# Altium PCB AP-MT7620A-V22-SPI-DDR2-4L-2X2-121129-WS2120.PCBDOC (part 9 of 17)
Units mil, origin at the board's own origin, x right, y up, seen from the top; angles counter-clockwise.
Board outline 7316 x 4279 mil, 4 copper layers (Top, Inner Layer 2, Inner Layer 3, Bottom), stack 35.4 mil thick; 640 components, 473 nets, 2041 pads, 2358 vias.
Unrouted connection lines stored in the file: 11.
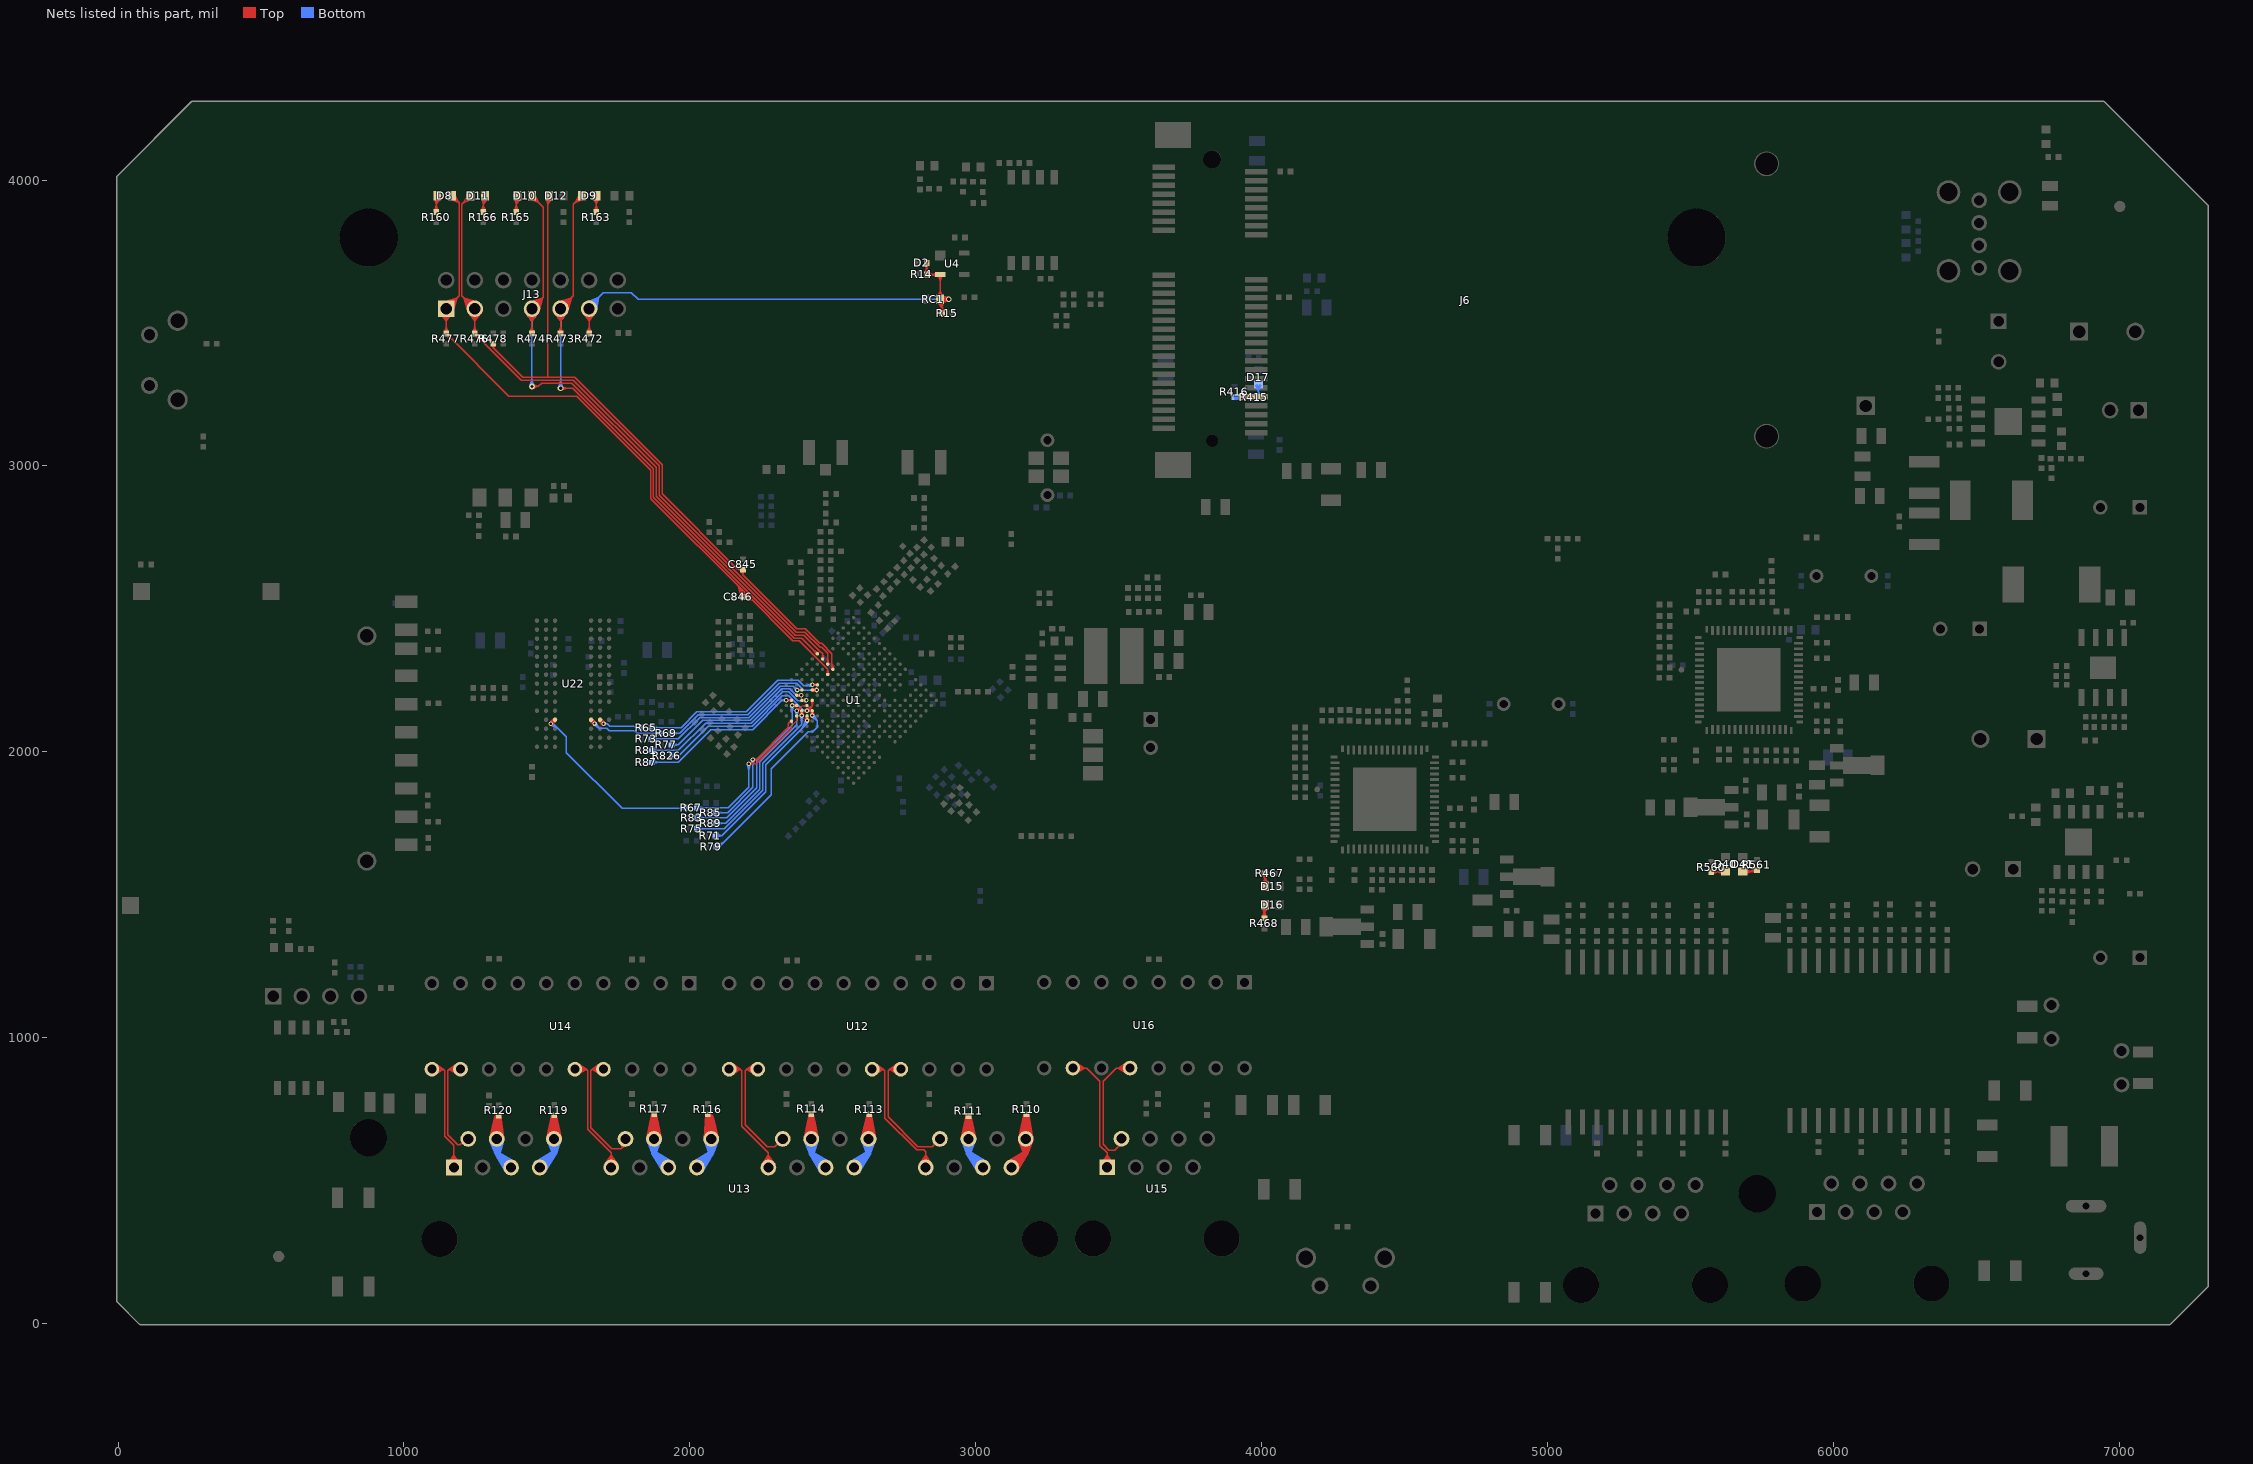
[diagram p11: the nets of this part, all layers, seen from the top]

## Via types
v1: diameter 20, hole 12, Top to Bottom, 2117 vias
v2: diameter 16, hole 8, Top to Bottom, 241 vias

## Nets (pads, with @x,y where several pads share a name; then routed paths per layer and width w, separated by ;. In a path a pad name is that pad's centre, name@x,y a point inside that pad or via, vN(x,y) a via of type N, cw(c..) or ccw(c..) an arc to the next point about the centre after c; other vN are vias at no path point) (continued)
JTAGRST_N: D2.1 J13.11 R14.2 R15.1 R472.2 RC1.1 U4.2 | length 4977.9
  Top w4.5: J13.11@1622.61,3541.58 1648,3507.5 ; J13.11@1626.53,3544.18 1648,3507.5 ; J13.11@1630.64,3546.29 1648,3507.5 ; J13.11@1634.91,3547.93 1648,3507.5 ; J13.11@1639.3,3549.1 1648,3507.5 ; R472.2@1640.36,3464.28 1648,3486.5 ; R472.2@1644.76,3463.22 1648,3486.5 ; R472.2@1648,3463 J13.11@1648,3550 ; R472.2@1651.24,3463.22 1648,3486.5 ; R472.2@1655.64,3464.28 1648,3486.5 ; J13.11@1656.7,3549.1 1648,3507.5 ; J13.11@1661.09,3547.93 1648,3507.5 ; J13.11@1665.36,3546.29 1648,3507.5 ; J13.11@1669.47,3544.18 1648,3507.5 ; J13.11@1673.39,3541.58 1648,3507.5 ; D2.1@2821.36,3708.72 2829,3686.5 ; R14.2@2822.31,3670.95 2829,3693.53 ; D2.1@2825.76,3709.78 2829,3686.5 ; R14.2@2826.75,3670.09 2829,3693.53 ; R14.2@2830.11,3666.75 2853.52,3669.2 ; R14.2@2830.33,3673.23 2853.52,3669.2 ; R14.2@2831.02,3662.32 2853.52,3669.2 ; R14.2@2831.53,3677.6 2853.52,3669.2 ; D2.1@2832.24,3709.78 2829,3686.5 ; R14.2@2833.23,3670.36 2829,3693.53 ; D2.1@2836.64,3708.72 2829,3686.5 ; R14.2@2837.58,3671.6 2829,3693.53 ; RC1.1@2864.11,3587.51 2875.59,3612.5 ; RC1.1@2865.01,3575.88 2883,3552.18 ; U4.2@2865,3662.48 2843.48,3669.2 ; U4.2@2865,3675.93 2843.48,3669.2 ; U4.2@2865.91,3666.9 2843.48,3669.2 ; U4.2@2865.91,3671.51 2843.48,3669.2 ; U4.2@2866.03,3669.2 2843.48,3669.2 ; RC1.1@2868.4,3585.96 2875.59,3612.5 ; RC1.1@2868.84,3578.35 2883,3552.18 ; U4.2@2868.95,3668.2 2875.59,3646.65 ; RC1.1@2872.84,3585.14 2875.59,3612.5 ; RC1.1@2872.96,3580.19 2883,3552.18 ; U4.2@2873.37,3669.1 2875.59,3646.65 ; R15.1@2874.42,3536.6 2883,3558.53 ; RC1.1@2875.59,3581 2883,3552.18 ; RC1.1@2875.59,3585 2875.59,3612.5 ; RC1.1@2875.73,3580.25 v1@2903.09,3583 ; RC1.1@2875.73,3585.75 v1@2903.09,3583 ; RC1.1@2876.55,3575.81 v1@2903.09,3583 ; RC1.1@2876.55,3590.19 v1@2903.09,3583 ; U4.2@2877.98,3669.08 2875.59,3646.65 ; RC1.1@2878.1,3571.52 v1@2903.09,3583 ; RC1.1@2878.1,3594.48 v1@2903.09,3583 ; RC1.1@2878.28,3581.56 2883,3552.18 ; RC1.1@2878.34,3585.14 2875.59,3612.5 ; R15.1@2878.77,3535.36 2883,3558.53 ; U4.2@2882.4,3668.15 2875.59,3646.65 ; RC1.1@2882.78,3581.94 2883,3552.18 ; RC1.1@2882.78,3585.96 2875.59,3612.5 ; R15.1@2885.25,3535.09 2883,3558.53 ; RC1.1@2887.07,3587.51 2875.59,3612.5 ; RC1.1@2887.32,3581.62 2883,3552.18 ; R15.1@2889.69,3535.95 2883,3558.53 ; v1@2902.07,3576.32 RC1.1@2881.42,3592.95 ; v1@2902.07,3589.68 RC1.1@2881.42,3573.05 ; v1@2903.09,3575.82 RC1.1@2880.84,3589.02 ; v1@2903.09,3590.18 RC1.1@2880.84,3576.98 ; v1@2904.15,3575.47 RC1.1@2880.55,3585.26 ; v1@2904.15,3590.53 RC1.1@2880.55,3580.74 ; v1@2904.6,3580.07 RC1.1@2881.42,3592.95 ; v1@2904.6,3585.93 RC1.1@2881.42,3573.05 ; v1@2904.82,3575.34 RC1.1@2880.5,3583 ; v1@2904.82,3590.66 RC1.1@2880.5,3583 ; v1@2905.05,3579.89 RC1.1@2880.84,3589.02 ; v1@2905.05,3586.11 RC1.1@2880.84,3576.98 ; v1@2905.51,3575.27 RC1.1@2880.55,3580.74 ; v1@2905.51,3579.79 RC1.1@2880.55,3585.26 ; v1@2905.51,3586.21 RC1.1@2880.55,3580.74 ; v1@2905.51,3590.73 RC1.1@2880.55,3585.26 ; v1@2905.79,3579.76 RC1.1@2880.5,3583 ; v1@2905.79,3586.24 RC1.1@2880.5,3583 ; v1@2906.08,3579.75 RC1.1@2880.55,3580.74 ; v1@2906.08,3586.25 RC1.1@2880.55,3585.26 ; v1@2906.56,3579.8 RC1.1@2880.84,3576.98 ; v1@2906.56,3586.2 RC1.1@2880.84,3589.02 ; v1@2906.66,3575.28 RC1.1@2880.84,3576.98 ; v1@2906.66,3590.72 RC1.1@2880.84,3589.02 ; v1@2907.03,3579.92 RC1.1@2881.42,3573.05 ; v1@2907.03,3586.08 RC1.1@2881.42,3592.95 ; v1@2907.83,3575.47 RC1.1@2881.42,3573.05 ; v1@2907.83,3590.53 RC1.1@2881.42,3592.95 ; R14.2@2829,3670 R14.2@2830,3670 ; R14.2@2829,3670 2829.8,3669.2 U4.2@2875.68,3669.2 ; R14.2@2829,3670 D2.1@2829,3710 2829,3686.5 ; 2829,3693.53 R14.2@2830,3670 ; R14.2@2830,3670 2853.52,3669.2 ; RC1.1@2875.59,3583 2875.59,3669.12 U4.2@2875.68,3669.2 ; RC1.1@2875.59,3583 v1(2906,3583) ; RC1.1@2875.59,3583 2883,3575.59 2883,3535 R15.1@2882,3535 2883,3558.53 ; 2875.59,3646.65 U4.2@2875.68,3669.2 ; RC1.1@2880.5,3583 v1(2906,3583) ; RC1.1@2880.55,3580.74 v1(2906,3583) ; RC1.1@2880.55,3585.26 v1(2906,3583) ; RC1.1@2880.84,3576.98 v1(2906,3583) ; RC1.1@2880.84,3589.02 v1(2906,3583) ; RC1.1@2881.42,3573.05 v1(2906,3583) ; RC1.1@2881.42,3592.95 v1(2906,3583)
  Bottom w4.5: J13.11@1632.42,3571.75 1681.31,3590.31 ; J13.11@1634.26,3567.5 1681.31,3590.31 ; J13.11@1636.43,3563.47 1681.31,3590.31 ; J13.11@1638.94,3559.67 1681.31,3590.31 ; J13.11@1641.74,3556.12 1681.31,3590.31 ; J13.11@1648,3550 1650,3552 1650,3561 1652,3561 1697,3606 1796,3606 1819,3583 v1(2906,3583) 2880.5,3583 ; J13.11@1655.19,3545.01 1681.31,3590.31 ; J13.11@1659.2,3542.92 1681.31,3590.31 ; J13.11@1663.4,3541.18 1681.31,3590.31 ; J13.11@1667.78,3539.8 1681.31,3590.31 ; J13.11@1672.29,3538.8 1681.31,3590.31 ; v1@2904.82,3575.34 2880.5,3583 ; v1@2904.82,3590.66 2880.5,3583 ; v1@2905.79,3579.76 2880.5,3583 ; v1@2905.79,3586.24 2880.5,3583
LANLED0_IP1001-2_6-LED1: D40.2 R560.1 | length 363.3
  Top w4.5: R560.1@5572.89,1582.25 5596.71,1581.41 ; R560.1@5573.48,1586.74 5596.71,1581.41 ; R560.1@5573.55,1575.8 5596.71,1581.41 ; R560.1@5575.03,1571.52 5596.71,1581.41 ; D40.2@5618.49,1569.93 5593.5,1581.41 ; D40.2@5618.49,1592.89 5593.5,1581.41 ; D40.2@5620.04,1574.22 5593.5,1581.41 ; D40.2@5620.04,1588.6 5593.5,1581.41 ; D40.2@5620.86,1578.66 5593.5,1581.41 ; D40.2@5620.86,1584.16 5593.5,1581.41 ; D40.2@5621,1581.41 5593.5,1581.41 ; D40.2@5623,1581.41 5574.41,1581.41 5573,1580 R560.1@5573,1579 5596.71,1581.41
LANLED0_IP1001_6-LED1: D15.2 R467.1 | length 358.2
  Top w4.5: D15.2@4000.93,1534.51 4012.41,1559.5 ; R467.1@4002.52,1572.97 4012.41,1551.3 ; D15.2@4005.22,1532.96 4012.41,1559.5 ; R467.1@4006.8,1574.45 4012.41,1551.3 ; D15.2@4009.66,1532.14 4012.41,1559.5 ; D15.2@4012.41,1530 4012.41,1573.59 4011,1575 R467.1@4010,1575 4012.41,1551.3 ; D15.2@4012.41,1532 4012.41,1559.5 ; R467.1@4013.25,1575.11 4012.41,1551.3 ; D15.2@4015.16,1532.14 4012.41,1559.5 ; R467.1@4017.74,1574.52 4012.41,1551.3 ; D15.2@4019.6,1532.96 4012.41,1559.5 ; D15.2@4023.89,1534.51 4012.41,1559.5
LANLED1_6-LED1: D11.1 R166.1 | length 354.9
  Top w4.5: R166.1@1270.36,3889.28 1278,3911.5 ; D11.1@1271.84,3942.88 1278,3914.75 ; R166.1@1274.76,3888.22 1278,3911.5 ; D11.1@1276.36,3943.5 1278,3914.75 ; R166.1@1278,3888 1278,3939.41 D11.1@1283.59,3945 ; D11.1@1280.87,3943.4 1278,3914.75 ; R166.1@1281.24,3888.22 1278,3911.5 ; D11.1@1283.59,3943 1278,3914.75 ; R166.1@1285.64,3889.28 1278,3911.5 ; D11.1@1286.26,3942.34 1278,3914.75 ; D11.1@1290.47,3940.71 1278,3914.75 ; D11.1@1294.41,3938.42 1278,3914.75
LANLED2_6-LED1: D10.1 R165.1 | length 350.7
  Top w4.5: R165.1@1385.36,3889.28 1393,3911.5 ; D10.1@1385.68,3942.38 1393,3915.07 ; R165.1@1389.76,3888.22 1393,3911.5 ; D10.1@1390.16,3943.2 1393,3915.07 ; R165.1@1393,3888 1393,3940.59 D10.1@1397.41,3945 ; D10.1@1394.67,3943.3 1393,3915.07 ; R165.1@1396.24,3888.22 1393,3911.5 ; D10.1@1397.41,3943 1393,3915.07 ; D10.1@1400.1,3942.44 1393,3915.07 ; R165.1@1400.64,3889.28 1393,3911.5 ; D10.1@1404.37,3940.96 1393,3915.07 ; D10.1@1408.38,3938.8 1393,3915.07
LANLED2_IP1001-2_6-LED1: D41.2 R561.1 | length 382
  Top w4.5: D41.2@5683,1581.41 5683,1580 5733,1580 R561.1@5733,1587 ; D41.2@5685,1578.66 5712.53,1580 ; D41.2@5685,1581.41 5712.53,1580 ; D41.2@5685.28,1584.15 5712.53,1580 ; D41.2@5685.58,1574.18 5712.53,1580 ; D41.2@5686.32,1588.54 5712.53,1580 ; D41.2@5686.91,1569.82 5712.53,1580 ; D41.2@5688.09,1592.75 5712.53,1580 ; R561.1@5729.82,1594.07 5708.04,1580 ; R561.1@5731.93,1590.07 5708.04,1580 ; R561.1@5733,1588 R561.1@5733,1587 ; R561.1@5733.68,1583.82 5708.04,1580 ; R561.1@5733.95,1579.31 5708.04,1580 ; 5708.04,1580 R561.1@5733,1587
LANLED2_IP1001_6-LED1: D16.2 R468.1 | length 244
  Top w5: D16.2@4000.99,1461.67 4010,1433.91 ; R468.1@4002.58,1419.12 4010,1443 R468.1@4017.42,1419.12 ; D16.2@4005.91,1462.81 4010,1433.91 ; R468.1@4010,1418 4010,1462.59 D16.2@4012.41,1465 ; D16.2@4012.41,1463 4010,1433.91 ; D16.2@4018.79,1461.75 4010,1433.91 ; D16.2@4023.46,1459.81 4010,1433.91
LANLED3_6-LED1: D9.1 R163.1 | length 343.8
  Top w4.5: D9.1@1662.06,3940.74 1673,3915.49 ; R163.1@1665.36,3889.28 1673,3911.5 ; D9.1@1666.38,3942.2 1673,3915.49 ; R163.1@1669.76,3888.22 1673,3911.5 ; D9.1@1670.84,3942.92 1673,3915.49 ; R163.1@1673,3888 1673,3944.41 D9.1@1673.59,3945 ; D9.1@1673.59,3943 1673,3915.49 ; R163.1@1676.24,3888.22 1673,3911.5 ; D9.1@1676.33,3942.8 1673,3915.49 ; R163.1@1680.64,3889.28 1673,3911.5 ; D9.1@1680.76,3941.89 1673,3915.49 ; D9.1@1685.01,3940.25 1673,3915.49
LANLED4_6-LED1: D8.1 R160.1 | length 352.5
  Top w4.5: R160.1@1105.36,3889.28 1113,3911.5 ; D8.1@1105.68,3942.38 1113,3915.19 ; R160.1@1109.76,3888.22 1113,3911.5 ; D8.1@1110.16,3943.2 1113,3915.19 ; R160.1@1113,3888 1113,3945 D8.1@1117.41,3945 ; D8.1@1114.67,3943.3 1113,3915.19 ; R160.1@1116.24,3888.22 1113,3911.5 ; D8.1@1117.41,3943 1113,3915.19 ; D8.1@1120.1,3942.44 1113,3915.19 ; R160.1@1120.64,3889.28 1113,3911.5 ; D8.1@1124.36,3940.95 1113,3915.19 ; D8.1@1128.38,3938.78 1113,3915.19
LANP0_C1_4-ETHERNET: R120.1 U13.4 U13.5 | length 1035.3
  Top w20: U13.4@1307.56,648.06 R120.1@1325,721 ; U13.4@1307.76,649.35 R120.1@1332,728 ; U13.4@1325,654.16 R120.1@1332,728 ; U13.4@1342.44,648.06 R120.1@1325,721 ; U13.4@1342.55,646.38 R120.1@1332,728 ; R120.1@1325,721 U13.4@1325,646 R120.1@1332,728 ; R120.1@1325,721 R120.1@1332,728
  Bottom w20: U13.4@1307.87,642.12 1328,593 ; U13.4@1342.45,644.08 1328,593 ; U13.5@1361.05,535.33 1328,593 ; U13.5@1385.67,559.95 1328,593 ; 1328,593 U13.5@1375,546 1328,593 ; 1328,593 1328,643 U13.4@1325,646 1328,593
LANP0_C2_4-ETHERNET: R119.1 U13.7 U13.8 | length 980.1
  Top w20: U13.8@1507.54,647.88 R119.1@1525,728 ; U13.8@1507.56,648.07 R119.1@1526,729 ; U13.8@1525,658.96 R119.1@1526,729 ; U13.8@1542.46,647.88 R119.1@1525,728 ; U13.8@1542.48,647.65 R119.1@1526,729 ; R119.1@1525,728 U13.8@1525,646 R119.1@1526,729 ; R119.1@1525,728 R119.1@1526,729
  Bottom w20: U13.7@1464.16,559.81 1527,598 ; U13.7@1475,546 1527,598 ; U13.7@1488.81,535.16 1527,598 ; U13.8@1507.89,642.08 1527,598 ; U13.8@1542.38,643.51 1527,598 ; 1527,598 1527,644 U13.8@1525,646 1527,598
LANP1_C1_4-ETHERNET: R117.1 U13.12 U13.13 | length 1073.3
  Top w20: U13.12@1857.53,647.79 R117.1@1875,732 ; U13.12@1857.55,647.97 R117.1@1876,733 ; U13.12@1875,662.96 R117.1@1876,733 ; U13.12@1892.47,647.79 R117.1@1875,732 ; U13.12@1892.49,647.57 R117.1@1876,733 ; R117.1@1875,732 U13.12@1875,646 R117.1@1876,733 ; R117.1@1875,732 R117.1@1876,733
  Bottom w20: U13.12@1857.71,642.92 1875,596 ; U13.12@1892.29,642.92 1875,596 ; U13.13@1911.14,535.22 1875,596 ; U13.13@1935.78,559.86 1875,596 ; 1875,596 U13.13@1925,546 1875,596 ; 1875,596 U13.12@1875,646 1875,596
LANP1_C2_4-ETHERNET: R116.1 U13.15 U13.16 | length 1022.3
  Top w20: U13.16@2057.45,645.34 R116.1@2063,732 ; U13.16@2057.56,648.06 2075,721 ; U13.16@2075,657.42 R116.1@2063,732 ; U13.16@2092.06,650.17 R116.1@2063,732 ; U13.16@2092.44,648.06 2075,721 ; R116.1@2063,732 2064,732 2075,721 ; R116.1@2063,732 2075,721 ; R116.1@2063,732 2075,721 ; R116.1@2063,732 U13.16@2075,646 2075,721
  Bottom w20: U13.15@2014.22,559.86 2075,596 ; U13.15@2025,546 2075,596 ; U13.15@2038.86,535.22 2075,596 ; U13.16@2057.71,642.92 2075,596 ; U13.16@2092.29,642.92 2075,596 ; 2075,596 U13.16@2075,646 2075,596
LANP2_C1_4-ETHERNET: R114.1 U13.20 U13.21 | length 1073.6
  Top w20: U13.20@2425,663 R114.1@2425,733 ; R114.1@2425,733 U13.20@2425,646 R114.1@2425,733 ; R114.1@2425,733 2407.53,647.77 R114.1@2425,733 ; R114.1@2425,733 2442.47,647.77 R114.1@2425,733
  Bottom w20: U13.20@2407.77,642.64 2426,595 ; U13.20@2442.35,643.32 2426,595 ; U13.21@2461.11,535.26 2426,595 ; U13.21@2485.74,559.89 2426,595 ; 2426,595 U13.21@2475,546 2426,595 ; 2426,595 2426,645 U13.20@2425,646 2426,595
LANP2_C2_4-ETHERNET: R113.1 U13.23 U13.24 | length 1091.7
  Top w20: U13.24@2628,662 R113.1@2628,732 ; U13.24@2625,646 2628,643 R113.1@2628,732 ; U13.24@2625,646 R113.1@2628,732 ; U13.24@2625,646 R113.1@2628,732 ; R113.1@2628,732 2607.61,648.4 R113.1@2628,732 ; R113.1@2628,732 2642.52,647.18 R113.1@2628,732
  Bottom w20: U13.23@2564.22,559.86 2625,596 ; U13.23@2575,546 2625,596 ; U13.23@2588.86,535.22 2625,596 ; U13.24@2607.71,642.92 2625,596 ; U13.24@2642.29,642.92 2625,596 ; 2625,596 U13.24@2625,646 2625,596
LANP3_C1_4-ETHERNET: R111.1 U13.28 U13.29 | length 1032.8
  Top w20: U13.28@2975,656 R111.1@2975,726 ; R111.1@2975,726 U13.28@2975,646 R111.1@2975,726 ; R111.1@2975,726 2957.55,647.93 R111.1@2975,726 ; R111.1@2975,726 2992.45,647.93 R111.1@2975,726
  Bottom w20: U13.28@2957.71,642.92 2975,596 ; U13.28@2992.29,642.92 2975,596 ; U13.29@3011.14,535.22 2975,596 ; U13.29@3035.78,559.86 2975,596 ; 2975,596 U13.29@3025,546 2975,596 ; 2975,596 U13.28@2975,646 2975,596
LANP3_C2_4-ETHERNET: R110.1 U13.31 U13.32 | length 994.1
  Top w20: U13.31@3114.22,559.86 3175,596 ; U13.31@3125,546 3175,596 ; U13.31@3138.86,535.22 3175,596 ; U13.32@3157.54,647.86 R110.1@3175,729 ; U13.32@3157.61,648.4 R110.1@3178,732 ; U13.32@3157.71,642.92 3175,596 ; U13.32@3175,661.51 R110.1@3178,732 ; U13.32@3192.29,642.92 3175,596 ; U13.32@3192.46,647.86 R110.1@3175,729 ; U13.32@3192.52,647.18 R110.1@3178,732 ; 3175,596 U13.32@3175,646 ; 3175,596 U13.32@3175,646 ; U13.32@3175,646 R110.1@3175,729 ; U13.32@3175,646 R110.1@3178,732 ; R110.1@3175,729 R110.1@3178,732
LED_5592_5G: D17.2 R415.1 | length 342.6
  Bottom w4: D17.2@3977.32,3281.64 3989,3258.41 ; D17.2@3981.1,3283.18 3989,3258.41 ; R415.1@3983.03,3240.73 3989,3262.11 ; D17.2@3985.01,3284.1 3989,3258.41 ; R415.1@3987,3240 3989,3262.11 ; R415.1@3988,3238 3989,3239 D17.2@3989,3284.41 3989,3258.41 ; R415.1@3991,3240 3989,3262.11 ; D17.2@3992.99,3284.1 3989,3258.41 ; R415.1@3994.94,3240.72 3989,3262.11 ; D17.2@3996.9,3283.18 3989,3258.41 ; R415.1@3998.71,3242.14 3989,3262.11 ; D17.2@4000.68,3281.64 3989,3258.41
  Bottom w4.5: R415.1@3988,3238 R415.1@3990,3240
LED_LKACT#_A_3-WLAN: J6.44 R415.2 R416.2 | length 2386.9
  Top w4: v1@3926.99,3247.74 J6.44@3949.8,3249.55 ; v1@3927.66,3243.77 J6.44@3949.8,3249.55 ; v1@3928.3,3232.03 J6.44@3949.8,3234.15 ; v1@3928.28,3236.07 J6.44@3949.8,3234.15 ; v1@3928.34,3243.95 J6.44@3950.95,3245.68 ; v1@3928.39,3247.98 J6.44@3950.95,3245.68 ; v1@3929,3236 J6.44@3950.95,3238.02 ; v1@3929.02,3244 J6.44@3953.07,3241.85 ; v1@3929.03,3244 J6.44@3951.31,3241.85 ; v1@3929.64,3236.05 J6.44@3953.07,3241.85 ; v1@3929.69,3236.06 J6.44@3951.31,3241.85 ; v1@3929.72,3243.93 J6.44@3950.95,3238.02 ; v1@3929.72,3247.97 J6.44@3953.07,3241.85 ; v1@3929.74,3232.03 J6.44@3950.95,3238.02 ; v1@3929.77,3247.96 J6.44@3951.31,3241.85 ; v1@3930.34,3236.23 J6.44@3950.95,3245.68 ; v1@3930.43,3243.73 J6.44@3949.8,3234.15 ; v1@3930.93,3232.24 J6.44@3953.07,3241.85 ; v1@3930.98,3236.52 J6.44@3949.8,3249.55 ; v1@3931.08,3232.27 J6.44@3951.31,3241.85 ; v1@3931.15,3247.71 J6.44@3950.95,3238.02 ; v1@3932.34,3232.73 J6.44@3950.95,3245.68 ; v1@3932.55,3247.17 J6.44@3949.8,3234.15 ; v1@3933.56,3233.42 J6.44@3949.8,3249.55 ; J6.44@3962,3241.85 v1@3930.85,3241.85 ; v1(3929,3240) v1@3930.85,3241.85 ; v1(3929,3240) J6.44@3953.07,3241.85 ; v1(3929,3240) J6.44@3949.8,3234.15 ; v1(3929,3240) J6.44@3949.8,3249.55 ; v1(3929,3240) J6.44@3950.95,3238.02 ; v1(3929,3240) J6.44@3950.95,3245.68 ; v1(3929,3240) J6.44@3951.31,3241.85 ; v1@3930.85,3241.85 J6.44@3949.8,3234.15 ; v1@3930.85,3241.85 J6.44@3949.8,3249.55 ; v1@3930.85,3241.85 J6.44@3950.95,3238.02 ; v1@3930.85,3241.85 J6.44@3950.95,3245.68 ; v1@3930.85,3241.85 J6.44@3951.31,3241.85
  Top w4.5: J6.44@3962,3241.85 J6.44@3980.83,3241.85
  Bottom w4: v1@3924.92,3233.12 R416.2@3906.09,3248.92 ; v1@3925.38,3247.13 R416.2@3906.81,3233.21 ; v1@3926.09,3232.55 R416.2@3905.19,3244.99 ; v1@3926.67,3247.65 R416.2@3905.54,3237.04 ; v1@3927.02,3232.25 R416.2@3905,3242 ; v1@3927.25,3236.4 R416.2@3906.09,3248.92 ; v1@3927.34,3232.17 R416.2@3905,3241 ; v1@3927.5,3243.71 R416.2@3906.81,3233.21 ; v1@3927.85,3232.08 R415.2@3952.5,3232.54 ; v1@3927.86,3236.17 R416.2@3905.19,3244.99 ; v1@3927.85,3247.92 R415.2@3952.5,3247.46 ; v1@3928,3247.94 R416.2@3905,3241 ; v1@3928.1,3236.1 R415.2@3952.5,3232.54 ; v1@3928.1,3243.9 R415.2@3952.5,3247.46 ; v1@3928.16,3243.91 R416.2@3905.54,3237.04 ; v1@3928.34,3236.06 R416.2@3905,3242 ; v1@3928.33,3247.97 R416.2@3905,3242 ; v1@3928.5,3236.03 R416.2@3905,3241 ; v1@3928.65,3232.01 R416.2@3905.54,3237.04 ; v1@3928.72,3236.01 R415.2@3952.88,3236.34 ; v1@3928.72,3243.99 R415.2@3952.88,3243.66 ; v1@3928.83,3244 R416.2@3905,3241 ; v1@3929,3244 R416.2@3905,3242 ; v1@3929.11,3232 R415.2@3952.88,3236.34 ; v1@3929.11,3248 R415.2@3952.88,3243.66 ; v1@3929.16,3236 R416.2@3905.54,3237.04 ; v1@3929.33,3236.01 R415.2@3953,3240 ; v1@3929.33,3243.99 R415.2@3953,3240 ; v1@3929.33,3247.99 R416.2@3905.19,3244.99 ; v1@3929.5,3243.97 R416.2@3905.19,3244.99 ; v1@3929.84,3236.09 R416.2@3906.81,3233.21 ; v1@3929.93,3236.11 R415.2@3952.88,3243.66 ; v1@3929.93,3243.89 R415.2@3952.88,3236.34 ; v1@3929.99,3232.06 R416.2@3906.81,3233.21 ; v1@3930.14,3243.83 R416.2@3906.09,3248.92 ; v1@3930.33,3232.11 R415.2@3953,3240 ; v1@3930.33,3247.89 R415.2@3953,3240 ; v1@3930.52,3236.3 R415.2@3952.5,3247.46 ; v1@3930.52,3243.7 R415.2@3952.5,3232.54 ; v1@3930.65,3247.83 R416.2@3906.09,3248.92 ; v1@3931.5,3232.4 R415.2@3952.88,3243.66 ; v1@3931.5,3247.6 R415.2@3952.88,3236.34 ; v1@3932.63,3232.87 R415.2@3952.5,3247.46 ; v1@3932.63,3247.13 R415.2@3952.5,3232.54 ; R415.2@3953.55,3232.13 v1@3933,3240 ; R415.2@3953.55,3247.87 v1@3933,3240 ; R415.2@3954.64,3236.02 v1@3933,3240 ; R415.2@3954.64,3243.98 v1@3933,3240 ; R415.2@3955,3240 v1(3929,3240) ; R416.2@3905,3241 R416.2@3905,3242 ; R416.2@3905,3241 v1@3927,3242 ; R416.2@3905,3241 v1(3929,3240) ; R416.2@3905,3242 v1@3927,3242 ; R416.2@3905,3242 v1(3929,3240) ; R416.2@3905.18,3245 v1@3927,3242 ; R416.2@3905.19,3244.99 v1(3929,3240) ; R416.2@3905.54,3237.04 v1@3927,3242 ; R416.2@3905.54,3237.04 v1(3929,3240) ; R416.2@3906.09,3248.92 v1@3927,3242 ; R416.2@3906.09,3248.92 v1(3929,3240) ; R416.2@3906.81,3233.21 v1@3927,3242 ; R416.2@3906.81,3233.21 v1(3929,3240) ; v1@3927,3242 v1(3929,3240) ; v1(3929,3240) R415.2@3952.5,3232.54 ; v1(3929,3240) R415.2@3952.5,3247.46 ; v1(3929,3240) R415.2@3952.88,3236.34 ; v1(3929,3240) R415.2@3952.88,3243.66
LINK0: C845.1 D12.2 R478.2 U1.H4 | length 2845.7
  Top w4.5: R478.2@1305.55,3424.85 1313,3413 ; R478.2@1309.77,3426.62 1313,3413 ; R478.2@1313,3427 1313,3413 ; R478.2@1316.23,3426.62 1313,3413 ; R478.2@1320.45,3424.85 1313,3413 ; D12.2@1495.68,3942.38 1503,3914.93 ; D12.2@1500.16,3943.2 1503,3914.93 ; D12.2@1504.67,3943.29 1503,3914.93 ; D12.2@1507.41,3943 1503,3914.93 ; D12.2@1507.41,3945 1503,3945 1503,3310 ; D12.2@1510.1,3942.44 1503,3914.93 ; D12.2@1514.37,3940.97 1503,3914.93 ; D12.2@1518.39,3938.82 1503,3914.93 ; 2165,2640 1903,2902 1903,3005 1598,3310 1503,3310 ; C845.1@2178.41,2636.42 2186,2619 ; C845.1@2182.76,2637.72 2186,2619 ; C845.1@2186,2638 2186,2619 ; C845.1@2189.24,2637.72 2186,2619 ; C845.1@2193.59,2636.42 2186,2619 ; U1.H4@2496.98,2288.27 2497,2310.49 ; U1.H4@2504.16,2289.46 2497,2310.49 ; 1313,3413 1416,3310 1503,3310 ; 2186,2619 2375,2430 2404.43,2430 2455.43,2379 2461,2379 2497,2343 2497,2288.57 U1.H4@2500.62,2288.57 2497,2310.49
  Top w5: 2165,2640 2167,2638 ; C845.1@2184.52,2630.65 2167,2638 ; C845.1@2184.52,2645.35 2167,2638 ; C845.1@2186,2638 2167,2638
LINK1: D11.2 J13.3 R476.2 U1.H3 | length 3799.1
  Top w4.5: J13.3@1222.61,3541.58 1248,3507.5 ; D11.2@1223.02,3950.06 1208.86,3921.45 ; J13.3@1225.02,3536.3 1209.45,3588.55 ; J13.3@1226.53,3544.18 1248,3507.5 ; D11.2@1226.94,3947.76 1208.86,3921.45 ; J13.3@1229.39,3537.81 1209.45,3588.55 ; D11.2@1230.47,3944.95 1208.86,3921.45 ; J13.3@1230.64,3546.29 1248,3507.5 ; D11.2@1232.41,3943 1208.86,3921.45 ; D11.2@1232.41,3945 1203,3915.59 1203,3595 J13.3@1248,3550 R476.2@1248,3463 ; J13.3@1233.57,3539.66 1209.45,3588.55 ; D11.2@1234.18,3940.89 1208.86,3921.45 ; J13.3@1234.91,3547.93 1248,3507.5 ; D11.2@1236.66,3937.13 1208.86,3921.45 ; J13.3@1237.56,3541.84 1209.45,3588.55 ; D11.2@1238.61,3933.02 1208.86,3921.45 ; J13.3@1239.3,3549.1 1248,3507.5 ; R476.2@1240.36,3464.28 1248,3486.5 ; J13.3@1241.34,3544.33 1209.45,3588.55 ; R476.2@1243.19,3456.92 1266.92,3443.08 ; R476.2@1244.76,3463.22 1248,3486.5 ; R476.2@1245.78,3460.63 1266.92,3443.08 ; R476.2@1250.49,3465.1 1266.92,3443.08 ; R476.2@1251.24,3463.22 1248,3486.5 ; J13.3@1253.67,3556.66 1209.45,3588.55 ; R476.2@1254.32,3467.49 1266.92,3443.08 ; R476.2@1255.64,3464.28 1248,3486.5 ; J13.3@1256.16,3560.44 1209.45,3588.55 ; J13.3@1256.7,3549.1 1248,3507.5 ; J13.3@1258.34,3564.43 1209.45,3588.55 ; J13.3@1260.19,3568.61 1209.45,3588.55 ; J13.3@1261.09,3547.93 1248,3507.5 ; J13.3@1261.7,3572.98 1209.45,3588.55 ; J13.3@1265.36,3546.29 1248,3507.5 ; J13.3@1269.47,3544.18 1248,3507.5 ; J13.3@1273.39,3541.58 1248,3507.5 ; U1.H3@2478.88,2306.97 2482.52,2328.52 ; U1.H3@2486.17,2306.97 2482.52,2328.52 ; R476.2@1248,3463 1248,3462 1284,3426 1284,3425.75 1311.75,3398 1312,3398 1410,3300 1593,3300 1893,3000 1893,2898 2373,2418 2402.82,2418 2455.82,2365 2461.57,2365 2482.52,2344.04 U1.H3@2482.52,2306.67 2482.52,2328.52 ; R476.2@1248,3463 1266.92,3443.08
LINK2: D10.2 J13.7 R474.2 U1.H2 | length 4237.6
  Top w4.5: J13.7@1422.61,3541.58 1448,3507.5 ; J13.7@1426.53,3544.18 1448,3507.5 ; J13.7@1430.64,3546.29 1448,3507.5 ; J13.7@1434.3,3572.98 1486.55,3588.55 ; J13.7@1434.91,3547.93 1448,3507.5 ; J13.7@1435.81,3568.61 1486.55,3588.55 ; J13.7@1437.66,3564.43 1486.55,3588.55 ; J13.7@1439.3,3549.1 1448,3507.5 ; J13.7@1439.84,3560.44 1486.55,3588.55 ; R474.2@1440.36,3464.28 1448,3486.5 ; D10.2@1442.11,3933.2 1471.76,3920.65 ; J13.7@1442.33,3556.66 1486.55,3588.55 ; D10.2@1444.18,3937.25 1471.76,3920.65 ; R474.2@1444.76,3463.22 1448,3486.5 ; D10.2@1446.77,3940.94 1471.76,3920.65 ; v1(1448,3278) 1469.66,3278 ; R474.2@1448,3463 J13.7@1448,3550 1488,3590 1488,3904.41 1448,3944.41 D10.2@1448.59,3945 ; v1@1448.24,3274.76 1469.66,3278 ; v1@1448.24,3281.24 1469.66,3278 ; D10.2@1448.59,3943 1471.76,3920.65 ; v1@1449.39,3270.38 1469.66,3278 ; v1@1449.39,3285.62 1469.66,3278 ; D10.2@1450.58,3944.9 1471.76,3920.65 ; R474.2@1451.24,3463.22 1448,3486.5 ; D10.2@1454.18,3947.62 1471.76,3920.65 ; J13.7@1454.66,3544.33 1486.55,3588.55 ; R474.2@1455.64,3464.28 1448,3486.5 ; J13.7@1456.7,3549.1 1448,3507.5 ; D10.2@1458.15,3949.83 1471.76,3920.65 ; J13.7@1458.44,3541.84 1486.55,3588.55 ; J13.7@1461.09,3547.93 1448,3507.5 ; J13.7@1462.43,3539.66 1486.55,3588.55 ; J13.7@1465.36,3546.29 1448,3507.5 ; J13.7@1466.61,3537.81 1486.55,3588.55 ; J13.7@1469.47,3544.18 1448,3507.5 ; J13.7@1470.98,3536.3 1486.55,3588.55 ; J13.7@1473.39,3541.58 1448,3507.5 ; U1.H2@2460.79,2325.12 2464.43,2343.37 ; U1.H2@2468.07,2325.12 2464.43,2343.37 ; 1469.66,3278 1481.66,3290 1588,3290 1883,2995 1883,2894 2369,2408 2399.2,2408 2451.2,2356 2451.8,2356 2464.43,2343.37 ; 2464.43,2343.37 U1.H2@2464.43,2324.76 2464.43,2343.37
  Bottom w4.5: J13.7@1422.61,3541.58 1448,3507.5 ; J13.7@1426.53,3544.18 1448,3507.5 ; J13.7@1430.64,3546.29 1448,3507.5 ; J13.7@1434.91,3547.93 1448,3507.5 ; J13.7@1439.3,3549.1 1448,3507.5 ; v1@1440.34,3279.18 1448,3303.5 ; v1@1444.76,3278.21 1448,3303.5 ; v1(1448,3278) J13.7@1448,3550 ; v1@1451.24,3278.21 1448,3303.5 ; v1@1455.66,3279.18 1448,3303.5 ; J13.7@1456.7,3549.1 1448,3507.5 ; J13.7@1461.09,3547.93 1448,3507.5 ; J13.7@1465.36,3546.29 1448,3507.5 ; J13.7@1469.47,3544.18 1448,3507.5 ; J13.7@1473.39,3541.58 1448,3507.5
LINK3: D9.2 J13.9 R473.2 U1.H1 | length 4107.3
  Top w4.5: J13.9@1522.61,3541.58 1548,3507.5 ; J13.9@1526.53,3544.18 1548,3507.5 ; J13.9@1530.64,3546.29 1548,3507.5 ; J13.9@1534.3,3572.98 1586.55,3588.55 ; J13.9@1534.91,3547.93 1548,3507.5 ; J13.9@1535.81,3568.61 1586.55,3588.55 ; J13.9@1537.66,3564.43 1586.55,3588.55 ; J13.9@1539.3,3549.1 1548,3507.5 ; J13.9@1539.84,3560.44 1586.55,3588.55 ; R473.2@1540.36,3464.28 1548,3486.5 ; J13.9@1542.33,3556.66 1586.55,3588.55 ; R473.2@1544.76,3463.22 1548,3486.5 ; v1(1548,3272) 1591,3272 1873,2990 1873,2890 2365,2398 2391.19,2398 U1.H1@2446.33,2342.86 2432.61,2356.58 ; R473.2@1548,3463 J13.9@1548,3550 1593,3595 1593,3915.59 D9.2@1622.41,3945 ; v1@1548.21,3268.76 1573.5,3272 ; v1@1548.21,3275.24 1573.5,3272 ; v1@1549.18,3264.34 1573.5,3272 ; v1@1549.18,3279.66 1573.5,3272 ; R473.2@1551.24,3463.22 1548,3486.5 ; J13.9@1554.66,3544.33 1586.55,3588.55 ; R473.2@1555.64,3464.28 1548,3486.5 ; J13.9@1556.7,3549.1 1548,3507.5 ; J13.9@1558.44,3541.84 1586.55,3588.55 ; J13.9@1561.09,3547.93 1548,3507.5 ; J13.9@1562.43,3539.66 1586.55,3588.55 ; J13.9@1565.36,3546.29 1548,3507.5 ; J13.9@1566.61,3537.81 1586.55,3588.55 ; J13.9@1569.47,3544.18 1548,3507.5 ; J13.9@1570.98,3536.3 1586.55,3588.55 ; J13.9@1573.39,3541.58 1548,3507.5 ; D9.2@1613.02,3950.06 1598.86,3921.45 ; D9.2@1616.94,3947.76 1598.86,3921.45 ; D9.2@1620.47,3944.95 1598.86,3921.45 ; D9.2@1622.41,3943 1598.86,3921.45 ; D9.2@1624.18,3940.89 1598.86,3921.45 ; D9.2@1626.66,3937.13 1598.86,3921.45 ; D9.2@1628.61,3933.02 1598.86,3921.45 ; U1.H1@2443.52,2340.53 2432.61,2356.58 ; U1.H1@2448.66,2345.67 2432.61,2356.58
  Bottom w4.5: J13.9@1522.61,3541.58 1548,3507.5 ; J13.9@1526.53,3544.18 1548,3507.5 ; J13.9@1530.64,3546.29 1548,3507.5 ; J13.9@1534.91,3547.93 1548,3507.5 ; J13.9@1539.3,3549.1 1548,3507.5 ; v1@1540.34,3273.18 1548,3297.5 ; v1@1544.76,3272.21 1548,3297.5 ; v1(1548,3272) J13.9@1548,3550 ; v1@1551.24,3272.21 1548,3297.5 ; v1@1555.66,3273.18 1548,3297.5 ; J13.9@1556.7,3549.1 1548,3507.5 ; J13.9@1561.09,3547.93 1548,3507.5 ; J13.9@1565.36,3546.29 1548,3507.5 ; J13.9@1569.47,3544.18 1548,3507.5 ; J13.9@1573.39,3541.58 1548,3507.5
LINK4: C846.1 D8.2 J13.1 R477.2 U1.J4 | length 4467.2
  Top w4.5: J13.1@1122.61,3541.58 1148,3507.5 ; J13.1@1126.53,3544.18 1148,3507.5 ; J13.1@1130.64,3546.29 1148,3507.5 ; J13.1@1134.3,3572.98 1186.55,3588.55 ; J13.1@1134.91,3547.93 1148,3507.5 ; J13.1@1135.81,3568.61 1186.55,3588.55 ; J13.1@1137.66,3564.43 1186.55,3588.55 ; J13.1@1139.3,3549.1 1148,3507.5 ; J13.1@1139.84,3560.44 1186.55,3588.55 ; R477.2@1140.36,3464.28 1148,3486.5 ; J13.1@1142.33,3556.66 1186.55,3588.55 ; R477.2@1143.42,3456.75 1167.79,3443.71 ; R477.2@1144.76,3463.22 1148,3486.5 ; R477.2@1145.87,3460.54 1167.79,3443.71 ; R477.2@1150.4,3465.19 1167.79,3443.71 ; R477.2@1151.24,3463.22 1148,3486.5 ; R477.2@1154.13,3467.74 1167.79,3443.71 ; J13.1@1154.66,3544.33 1186.55,3588.55 ; R477.2@1155.64,3464.28 1148,3486.5 ; J13.1@1156.7,3549.1 1148,3507.5 ; J13.1@1158.44,3541.84 1186.55,3588.55 ; J13.1@1161.09,3547.93 1148,3507.5 ; D8.2@1162.39,3933.02 1192.14,3921.45 ; J13.1@1162.43,3539.66 1186.55,3588.55 ; D8.2@1164.34,3937.13 1192.14,3921.45 ; J13.1@1165.36,3546.29 1148,3507.5 ; J13.1@1166.61,3537.81 1186.55,3588.55 ; D8.2@1166.82,3940.89 1192.14,3921.45 ; D8.2@1168.59,3943 1192.14,3921.45 ; D8.2@1168.59,3945 1193,3920.59 1193,3595 J13.1@1148,3550 R477.2@1148,3463 ; J13.1@1169.47,3544.18 1148,3507.5 ; D8.2@1170.53,3944.95 1192.14,3921.45 ; J13.1@1170.98,3536.3 1186.55,3588.55 ; J13.1@1173.39,3541.58 1148,3507.5 ; D8.2@1174.06,3947.76 1192.14,3921.45 ; D8.2@1177.98,3950.06 1192.14,3921.45 ; C846.1@2180.77,2539.2 2169.23,2579.77 ; C846.1@2185.04,2540.67 2169.23,2579.77 ; C846.1@2186.15,2534.47 2218.5,2530.5 ; C846.1@2187.01,2538.91 2218.5,2530.5 ; C846.1@2189.3,2544.98 2218.5,2530.5 ; C846.1@2190.85,2543.56 2169.23,2579.77 ; C846.1@2191.58,2548.88 2218.5,2530.5 ; C846.1@2194.59,2546.07 2169.23,2579.77 ; U1.J4@2478.89,2270.85 2482.52,2288.48 ; U1.J4@2482.52,2270.48 2482.52,2288.48 ; U1.J4@2486.16,2270.85 2482.52,2288.48 ; R477.2@1148,3463 1148,3462 1149.5,3462 1367.5,3244 1604,3244 1863,2985 1863,2886 2195,2554 ; R477.2@1148,3463 1167.79,3443.71 ; 2169.23,2579.77 C846.1@2188,2542 ; C846.1@2182.66,2547.62 2195,2554 ; C846.1@2182.66,2547.62 2195,2554 ; C846.1@2182.66,2547.62 2195,2554 ; C846.1@2185.4,2543.95 2195,2554 ; C846.1@2185.4,2543.95 2195,2554 ; C846.1@2185.4,2543.95 2195,2554 ; C846.1@2188,2542 2195,2549 2195,2554 ; C846.1@2188,2542 2195,2554 ; C846.1@2188,2542 2218.5,2530.5 ; C846.1@2188,2542 2195,2554 ; C846.1@2188,2542 2195,2554 ; C846.1@2190.98,2540.7 2195,2554 ; C846.1@2190.98,2540.7 2195,2554 ; C846.1@2190.98,2540.7 2195,2554 ; 2195,2554 2361,2388 2383,2388 2482.52,2288.48 ; 2195,2554 C846.1@2195.52,2540.12 ; 2195,2554 C846.1@2195.52,2540.12 ; 2195,2554 C846.1@2195.52,2540.12
MA0+_4-ETHERNET: U13.1 U14.11 | length 1214.3
  Top w5: U14.11@1098,890 1137,890 ; U14.11@1098.12,886.91 1137,890 ; U14.11@1098.12,893.09 1137,890 ; U14.11@1098.84,881.95 1137,890 ; U14.11@1098.84,898.05 1137,890 ; U14.11@1100.2,877.1 1137,890 ; U14.11@1100.2,902.9 1137,890 ; U14.11@1102.2,872.4 1137,890 ; U14.11@1102.2,907.6 1137,890 ; U14.11@1104.84,867.94 1137,890 ; U14.11@1104.84,912.06 1137,890 ; U13.1@1151.05,553.38 1175,588.56 ; U13.1@1155.51,550.73 1175,588.56 ; U13.1@1160.18,548.66 1175,588.56 ; U13.1@1165.01,547.19 1175,588.56 ; U13.1@1169.95,546.3 1175,588.56 ; U13.1@1175,546 1175,623.72 1142.5,656.22 1142.5,884.5 1137,890 ; U13.1@1180.05,546.3 1175,588.56 ; U13.1@1184.99,547.19 1175,588.56 ; U13.1@1189.82,548.66 1175,588.56 ; U13.1@1194.49,550.73 1175,588.56 ; U13.1@1198.95,553.38 1175,588.56
MA0-_4-ETHERNET: U13.2 U14.12 | length 753.1
  Top w5: U14.12@1191.16,867.94 1159,890 ; U14.12@1191.16,912.06 1159,890 ; U14.12@1193.8,872.4 1159,890 ; U14.12@1193.8,907.6 1159,890 ; U14.12@1195.8,877.1 1159,890 ; U14.12@1195.8,902.9 1159,890 ; U14.12@1197.16,881.95 1159,890 ; U14.12@1197.16,898.05 1159,890 ; U14.12@1197.88,886.91 1159,890 ; U14.12@1197.88,893.09 1159,890 ; U14.12@1198,890 1159,890 ; U13.2@1225,646 1196,625.5 1188.78,625.5 1153.5,660.78 1153.5,884.5 1159,890
MA0_1-CPU-RT0: R65.1 U1.L4 | length 840.7
  Top w8: U1.L4@2446.33,2234.29 v2(2428.9,2234.3) U1.L4@2446.33,2234.29
  Bottom w4.5: R65.1@1866,2085 1970,2085 2025,2140 2197,2140 2307,2250 2380,2250 2398.5,2231.5 2426.1,2231.5 v2(2428.9,2234.3) 2405.16,2231.5 ; R65.1@1866.22,2081.76 1889.5,2085 ; R65.1@1866.22,2088.24 1889.5,2085 ; R65.1@1867.28,2077.36 1889.5,2085 ; R65.1@1867.28,2092.64 1889.5,2085 ; v2@2427.54,2239.89 2405.16,2231.5 ; v2@2428.88,2228.55 2405.16,2231.5
MA1+_4-ETHERNET: U13.9 U14.16 | length 1235
  Top w5: U14.16@1598,890 1637,890 ; U14.16@1598.12,886.91 1637,890 ; U14.16@1598.12,893.09 1637,890 ; U14.16@1598.84,881.95 1637,890 ; U14.16@1598.84,898.05 1637,890 ; U14.16@1600.2,877.1 1637,890 ; U14.16@1600.2,902.9 1637,890 ; U14.16@1602.2,872.4 1637,890 ; U14.16@1602.2,907.6 1637,890 ; U14.16@1604.84,867.94 1637,890 ; U14.16@1604.84,912.06 1637,890 ; U13.9@1701.05,553.38 1725,588.56 ; U13.9@1705.51,550.73 1725,588.56 ; U13.9@1710.18,548.66 1725,588.56 ; U13.9@1715.01,547.19 1725,588.56 ; U13.9@1719.95,546.3 1725,588.56 ; U13.9@1725,546 1725,597.72 1642.5,680.22 1642.5,884.5 1637,890 ; U13.9@1730.05,546.3 1725,588.56 ; U13.9@1734.99,547.19 1725,588.56 ; U13.9@1739.82,548.66 1725,588.56 ; U13.9@1744.49,550.73 1725,588.56 ; U13.9@1748.95,553.38 1725,588.56
MA1-_4-ETHERNET: U13.10 U14.17 | length 1138.2
  Top w5: U14.17@1691.16,867.94 1659,890 ; U14.17@1691.16,912.06 1659,890 ; U14.17@1693.8,872.4 1659,890 ; U14.17@1693.8,907.6 1659,890 ; U14.17@1695.8,877.1 1659,890 ; U14.17@1695.8,902.9 1659,890 ; U14.17@1697.16,881.95 1659,890 ; U14.17@1697.16,898.05 1659,890 ; U14.17@1697.88,886.91 1659,890 ; U14.17@1697.88,893.09 1659,890 ; U14.17@1698,890 1659,890 ; U13.10@1749.94,645.56 1763,615.5 ; U13.10@1754.98,647.28 1763,615.5 ; U13.10@1760.09,648.15 1763,615.5 ; U13.10@1765.19,648.2 1763,615.5 ; U13.10@1770.16,647.48 1763,615.5 ; U13.10@1775,646 1763,615.5 ; U13.10@1779.55,643.79 1763,615.5 ; U13.10@1783.68,640.92 1763,615.5 ; U13.10@1787.37,637.41 1763,615.5 ; U13.10@1790.52,633.3 1763,615.5 ; U13.10@1793.04,628.61 1763,615.5 ; 1659,890 1653.5,884.5 1653.5,684.78 1726.39,611.89 1759.39,611.89 1763,615.5
MA1_1-CPU-RT0: R67.1 U1.T5 | length 814.3
  Top w4: 2355,2089.05 2373.95,2108 ; U1.T5@2370.07,2125.28 2373.95,2108 ; U1.T5@2377.83,2125.28 2373.95,2108 ; 2373.95,2108 U1.T5@2373.95,2125.71 2373.95,2108
  Top w4.5: v2(2206,1958) 2233,1958 2355,2080 2355,2089.05 ; v2@2206.7,1952.29 2229.5,1958 v2@2206.7,1963.71
  Bottom w4.5: R67.1@2024.09,1801.75 2047.54,1804 ; R67.1@2024.36,1808.23 2047.54,1804 ; R67.1@2024.95,1797.31 2047.54,1804 ; R67.1@2025.6,1812.58 2047.54,1804 ; v2@2200.29,1957.3 2206,1934.5 v2@2211.71,1957.3 ; v2(2206,1958) 2206,1876 2134,1804 2024,1804 2023,1805 R67.1@2024,1805 2047.54,1804
MA2+_4-ETHERNET: U12.11 U13.17 | length 1239.2
  Top w5: U12.11@2138,890 2177,890 ; U12.11@2138.12,886.91 2177,890 ; U12.11@2138.12,893.09 2177,890 ; U12.11@2138.84,881.95 2177,890 ; U12.11@2138.84,898.05 2177,890 ; U12.11@2140.2,877.1 2177,890 ; U12.11@2140.2,902.9 2177,890 ; U12.11@2142.2,872.4 2177,890 ; U12.11@2142.2,907.6 2177,890 ; U12.11@2144.84,867.94 2177,890 ; U12.11@2144.84,912.06 2177,890 ; U13.17@2251.05,553.38 2275,588.56 ; U13.17@2255.51,550.73 2275,588.56 ; U13.17@2260.18,548.66 2275,588.56 ; U13.17@2265.01,547.19 2275,588.56 ; U13.17@2269.95,546.3 2275,588.56 ; U13.17@2275,546 2275,598.22 2182.5,690.72 2182.5,884.5 2177,890 ; U13.17@2280.05,546.3 2275,588.56 ; U13.17@2284.99,547.19 2275,588.56 ; U13.17@2289.82,548.66 2275,588.56 ; U13.17@2294.49,550.73 2275,588.56 ; U13.17@2298.95,553.38 2275,588.56
MA2-_4-ETHERNET: U12.12 U13.18 | length 801.2
  Top w5: U12.12@2231.16,867.94 2199,890 ; U12.12@2231.16,912.06 2199,890 ; U12.12@2233.8,872.4 2199,890 ; U12.12@2233.8,907.6 2199,890 ; U12.12@2235.8,877.1 2199,890 ; U12.12@2235.8,902.9 2199,890 ; U12.12@2237.16,881.95 2199,890 ; U12.12@2237.16,898.05 2199,890 ; U12.12@2237.88,886.91 2199,890 ; U12.12@2237.88,893.09 2199,890 ; U12.12@2238,890 2199,890 ; U13.18@2325,646 2296.89,617.89 2270.89,617.89 2193.5,695.28 2193.5,884.5 2199,890
MA2_1-CPU-RT0: R69.1 U1.M4 | length 1014.2
  Top w4.5: v2@2442.07,2221.66 U1.M4@2428.65,2212.56 ; v2@2442.2,2211.09 U1.M4@2428.65,2219.82 ; v2@2444.6,2222.15 U1.M4@2428.65,2219.82 ; v2@2444.75,2210.66 U1.M4@2428.65,2212.56 ; U1.M4@2428.24,2216.19 v2@2444.4,2216.19 ; U1.M4@2428.24,2216.19 v2@2444.4,2216.19 ; U1.M4@2428.24,2216.19 2443.45,2210.73 U1.M4@2428.24,2216.19 ; U1.M4@2428.24,2216.19 2443.3,2222.04 U1.M4@2428.24,2216.19 ; U1.M4@2428.24,2216.19 v2(2444.4,2216.4) ; U1.M4@2428.24,2216.19 v2(2444.4,2216.4) ; U1.M4@2428.65,2212.56 v2@2444.4,2216.19 ; U1.M4@2428.65,2212.56 v2(2444.4,2216.4) ; U1.M4@2428.65,2219.82 v2@2444.4,2216.19 ; U1.M4@2428.65,2219.82 v2(2444.4,2216.4) ; v2@2444.4,2216.19 v2(2444.4,2216.4)
  Bottom w4.5: R69.1@1936,2065 1965,2065 2030,2130 2202.6,2130 2312.6,2240 2375,2240 2398.8,2216.2 2444.2,2216.2 v2(2444.4,2216.4) 2420.9,2216.2 ; R69.1@1936.22,2061.76 1959.5,2065 ; R69.1@1936.22,2068.24 1959.5,2065 ; R69.1@1937.28,2057.36 1959.5,2065 ; R69.1@1937.28,2072.64 1959.5,2065 ; v2@2443.65,2222.1 2420.9,2216.2 ; v2@2443.75,2210.69 2420.9,2216.2
MA3+_4-ETHERNET: U12.16 U13.25 | length 1275
  Top w5: U12.16@2638,890 2677,890 ; U12.16@2638.12,886.91 2677,890 ; U12.16@2638.12,893.09 2677,890 ; U12.16@2638.84,881.95 2677,890 ; U12.16@2638.84,898.05 2677,890 ; U12.16@2640.2,877.1 2677,890 ; U12.16@2640.2,902.9 2677,890 ; U12.16@2642.2,872.4 2677,890 ; U12.16@2642.2,907.6 2677,890 ; U12.16@2644.84,867.94 2677,890 ; U12.16@2644.84,912.06 2677,890 ; U13.25@2801.05,553.38 2825,588.56 ; U13.25@2805.51,550.73 2825,588.56 ; U13.25@2810.18,548.66 2825,588.56 ; U13.25@2815.01,547.19 2825,588.56 ; U13.25@2819.95,546.3 2825,588.56 ; U13.25@2825,546 2825,602 2819,608 2793.22,608 2682.5,718.72 2682.5,884.5 2677,890 ; U13.25@2830.05,546.3 2825,588.56 ; U13.25@2834.99,547.19 2825,588.56 ; U13.25@2839.82,548.66 2825,588.56 ; U13.25@2844.49,550.73 2825,588.56 ; U13.25@2848.95,553.38 2825,588.56
MA3-_4-ETHERNET: U12.17 U13.26 | length 833.9
  Top w5: U12.17@2731.16,867.94 2699,890 ; U12.17@2731.16,912.06 2699,890 ; U12.17@2733.8,872.4 2699,890 ; U12.17@2733.8,907.6 2699,890 ; U12.17@2735.8,877.1 2699,890 ; U12.17@2735.8,902.9 2699,890 ; U12.17@2737.16,881.95 2699,890 ; U12.17@2737.16,898.05 2699,890 ; U12.17@2737.88,886.91 2699,890 ; U12.17@2737.88,893.09 2699,890 ; U12.17@2738,890 2699,890 ; U13.26@2875,646 2848,619 2797.78,619 2693.5,723.28 2693.5,884.5 2699,890
MA3_1-CPU-RT0: R71.1 U1.R6 | length 872
  Top w4.5: v2@2404.46,2109.3 U1.R6@2406.51,2125.29 ; v2@2404.54,2110.61 U1.R6@2410.14,2125.71 ; v2@2404.91,2111.86 U1.R6@2413.78,2125.31 ; v2@2415.47,2111.89 U1.R6@2406.51,2125.29 ; v2@2415.85,2110.65 U1.R6@2410.14,2125.71 ; v2@2415.94,2109.34 U1.R6@2413.78,2125.31 ; U1.R6@2406.51,2125.29 v2(2410.2,2109.6) ; U1.R6@2410.14,2125.71 v2(2410.2,2109.6) ; v2(2410.2,2109.6) U1.R6@2413.78,2125.31
  Bottom w4.5: R71.1@2090,1707 2112,1707 ; R71.1@2090.24,1703.76 2112,1707 ; R71.1@2090.24,1710.24 2112,1707 ; R71.1@2091.37,1699.37 2112,1707 ; R71.1@2091.37,1714.63 2112,1707 ; v2@2405.07,2112.2 2394,2084 ; v2@2414.75,2106.08 2394,2084 ; 2112,1707 2265,1860 2265,1955 2410.2,2100.2 v2(2410.2,2109.6) 2394,2084
MA4+_4-ETHERNET: U15.1 U16.10 | length 1256.6
  Top w5: U16.10@3340,894 3388.41,894 3434.5,847.91 3434.5,622.78 3460,597.28 U15.1@3460,547 ; U16.10@3340.12,890.91 3380.59,894 ; U16.10@3340.12,897.09 3380.59,894 ; U16.10@3340.81,885.95 3380.59,894 ; U16.10@3340.81,902.05 3380.59,894 ; U16.10@3342.11,881.08 3380.59,894 ; U16.10@3342.11,906.92 3380.59,894 ; U16.10@3344.03,876.36 3380.59,894 ; U16.10@3344.03,911.64 3380.59,894 ; U16.10@3346.57,871.86 3380.59,894 ; U16.10@3346.57,916.14 3380.59,894 ; U15.1@3436.05,554.38 3460,589.56 ; U15.1@3440.51,551.73 3460,589.56 ; U15.1@3445.18,549.66 3460,589.56 ; U15.1@3450.01,548.19 3460,589.56 ; U15.1@3454.95,547.3 3460,589.56 ; U15.1@3465.05,547.3 3460,589.56 ; U15.1@3469.99,548.19 3460,589.56 ; U15.1@3474.82,549.66 3460,589.56 ; U15.1@3479.49,551.73 3460,589.56 ; U15.1@3483.95,554.38 3460,589.56
MA4-_4-ETHERNET: U15.2 U16.12 | length 836.2
  Top w5: U15.2@3510,647 3496.75,617.75 3486.17,607.17 3465.67,607.17 3445.5,627.34 3445.5,847.91 3491.59,894 U16.12@3540,894 ; U16.12@3533.43,871.86 3499.41,894 ; U16.12@3533.43,916.14 3499.41,894 ; U16.12@3535.97,876.36 3499.41,894 ; U16.12@3535.97,911.64 3499.41,894 ; U16.12@3537.89,881.08 3499.41,894 ; U16.12@3537.89,906.92 3499.41,894 ; U16.12@3539.19,885.95 3499.41,894 ; U16.12@3539.19,902.05 3499.41,894 ; U16.12@3539.88,890.91 3499.41,894 ; U16.12@3539.88,897.09 3499.41,894
MA4_1-CPU-RT0: R73.1 U1.N3 | length 789.3
  Top w4.5: v2(2376,2216) 2376.19,2216.19 v2@2377,2216.19
  Top w8: U1.N3@2392.05,2216.19 2377,2216.19 U1.N3@2392.05,2216.19 ; U1.N3@2392.05,2216.19 v2(2376,2216) U1.N3@2392.05,2216.19
  Bottom w4.5: R73.1@1866,2045 1960,2045 2035,2120 2207,2120 2317,2230 2362,2230 ; R73.1@1866.22,2041.76 1889.5,2045 ; R73.1@1866.22,2048.24 1889.5,2045 ; R73.1@1867.28,2037.36 1889.5,2045 ; R73.1@1867.28,2052.64 1889.5,2045 ; v2@2371.39,2212.57 2362,2230 ; v2(2376,2216) 2362,2230 ; v2@2379.43,2220.61 2362,2230
MA5_1-CPU-RT0: R75.1 U1.R5 | length 946.9
  Top w4.5: v2@2386.26,2126.75 U1.R5@2388.41,2143.42 ; v2@2386.69,2129.2 U1.R5@2395.68,2143.4 ; v2@2397.32,2129.17 U1.R5@2388.41,2143.42 ; v2@2397.67,2127.97 U1.R5@2392.05,2143.81 ; v2@2397.66,2127.99 U1.R5@2392.05,2143.81 ; v2@2397.74,2126.72 U1.R5@2395.68,2143.4 ; U1.R5@2388.41,2143.42 v2(2392,2127) ; v2(2392,2127) U1.R5@2392.05,2143.81 ; v2(2392,2127) U1.R5@2395.68,2143.4 ; v2(2392,2127) U1.R5@2392.05,2143.81 ; U1.R5@2392.05,2143.81 U1.R5@2392.05,2143.81 ; U1.R5@2392.05,2143.81 2386.34,2127.99 U1.R5@2392.05,2143.81
  Bottom w4.5: R75.1@2025,1731 2121,1731 2255,1865 2255,1960 2392,2097 v2(2392,2127) ; R75.1@2025.22,1727.76 2048.5,1731 ; R75.1@2025.22,1734.24 2048.5,1731 ; R75.1@2026.28,1723.36 2048.5,1731 ; R75.1@2026.28,1738.64 2048.5,1731 ; v2@2386.29,2126.3 2392,2103.5 v2@2397.71,2126.3
MA6_1-CPU-RT0: R77.1 U1.P3 | length 706.2
  Top w8: v2(2390,2198) U1.P3@2373.95,2198.1 v2@2390.1,2198.1
  Top w10: v2(2390,2198) v2@2390.1,2198.1
  Bottom w4.5: R77.1@1936,2025 1960.26,2025 2045.26,2110 2211,2110 2321,2220 2350,2220 2372,2198 ; R77.1@1936.22,2021.76 1959.5,2025 ; R77.1@1936.22,2028.24 1959.5,2025 ; R77.1@1937.28,2017.36 1959.5,2025 ; R77.1@1937.28,2032.64 1959.5,2025 ; v2@2389.08,2192.32 2372,2198 ; v2@2389.08,2203.68 2372,2198 ; v2(2390,2198) 2372,2198
MA7_1-CPU-RT0: R79.1 U1.P6 | length 1100.4
  Top w4.5: v2@2422.56,2126.71 U1.P6@2424.6,2143.41 ; v2@2422.97,2129.17 U1.P6@2431.87,2143.41 ; v2@2433.61,2129.2 U1.P6@2424.6,2143.41 ; v2@2434.05,2126.76 U1.P6@2431.87,2143.41 ; U1.P6@2424.6,2143.41 v2@2428.24,2127.06 ; U1.P6@2424.6,2143.41 v2(2428.3,2127) ; v2@2428.24,2127.06 U1.P6@2428.24,2143.81 ; v2@2428.24,2127.06 v2(2428.3,2127) ; v2@2428.24,2127.06 U1.P6@2431.87,2143.41 ; v2@2428.24,2127.06 U1.P6@2428.24,2143.81 ; U1.P6@2428.24,2143.81 2422.63,2127.96 U1.P6@2428.24,2143.81 ; U1.P6@2428.24,2143.81 2433.96,2128 U1.P6@2428.24,2143.81 ; U1.P6@2428.24,2143.81 v2(2428.3,2127) ; U1.P6@2428.24,2143.81 v2(2428.3,2127) ; v2(2428.3,2127) U1.P6@2431.87,2143.41
  Bottom w4.5: R79.1@2089.78,1675.05 2119.25,1684.25 ; R79.1@2091.44,1670.85 2119.25,1684.25 ; R79.1@2094.85,1665.33 2119.25,1684.25 ; R79.1@2097.87,1661.97 2119.25,1684.25 ; v2@2424.73,2122.49 2446,2109.3 ; v2(2428.3,2127) 2446,2109.3 ; v2@2432.81,2130.57 2446,2109.3 ; 2119.25,1684.25 R79.1@2093,1668 2103,1668 2285,1850 2285,1940 2415,2070 2430,2070 2446,2086 2446,2109.3
MA8_1-CPU-RT0: R81.1 U1.P4 | length 869
  Top w8: U1.P4@2392.05,2180 v2(2408,2180) ; U1.P4@2392.05,2180 v2(2408,2180) ; U1.P4@2392.05,2180 v2(2408,2180) ; U1.P4@2392.05,2180 v2(2408,2180)
  Bottom w4.5: R81.1@1866,2005 1960,2005 2055,2100 2214.5,2100 2324.5,2210 2346,2210 2377.3,2178.7 2406.7,2178.7 v2(2408,2180) 2384.46,2178.7 ; R81.1@1866.22,2001.76 1889.5,2005 ; R81.1@1866.22,2008.24 1889.5,2005 ; R81.1@1867.28,1997.36 1889.5,2005 ; R81.1@1867.28,2012.64 1889.5,2005 ; v2@2406.99,2185.66 2384.46,2178.7 ; v2@2407.61,2174.26 2384.46,2178.7
MA9_1-CPU-RT0: R83.1 U1.R4 | length 876.5
  Top w4.5: v2@2357.65,2156.36 U1.R4@2373.49,2158.28 ; v2@2357.79,2167.85 U1.R4@2373.58,2165.54 ; v2@2358.97,2156.43 U1.R4@2373.95,2161.9 ; v2@2359.11,2167.74 U1.R4@2373.95,2161.9 ; v2@2360.23,2156.8 U1.R4@2373.58,2165.54 ; v2@2360.36,2167.34 U1.R4@2373.49,2158.28 ; v2(2358,2162.1) U1.R4@2373.95,2161.9 ; v2(2358,2162.1) U1.R4@2373.49,2158.28 ; v2(2358,2162.1) U1.R4@2373.58,2165.54
  Bottom w4.5: R83.1@2025,1769 2129,1769 2235,1875 2235,1970 2358,2093 v2(2358,2162.1) ; R83.1@2025.22,1765.76 2048.5,1769 ; R83.1@2025.22,1772.24 2048.5,1769 ; R83.1@2026.28,1761.36 2048.5,1769 ; R83.1@2026.28,1776.64 2048.5,1769 ; v2@2352.29,2161.4 2358,2138.6 v2@2363.71,2161.4
MA10_1-CPU-RT0: R85.1 U1.U5 | length 694.6
  Top w4.5: v2(2220,1973) 2232,1973 ; v2@2221.38,1967.42 2232,1973 ; v2@2221.38,1978.58 2232,1973 ; U1.U5@2353.11,2110.03 2345,2098 ; U1.U5@2357.92,2104.6 2345,2098 ; 2232,1973 2345,2086 2345,2098 ; 2345,2098 2354.62,2107.62 U1.U5@2355.86,2107.62 2345,2098
  Bottom w4.5: R85.1@2091,1787 2132,1787 2220.5,1875.5 2220.5,1970.5 2220,1971 v2(2220,1973) 2220.5,1949.49 ; R85.1@2091.22,1783.76 2114.5,1787 ; R85.1@2091.22,1790.24 2114.5,1787 ; R85.1@2092.28,1779.36 2114.5,1787 ; R85.1@2092.28,1794.64 2114.5,1787 ; v2@2214.31,1972.18 2220.5,1949.49 ; v2@2225.72,1972.42 2220.5,1949.49
MA11_1-CPU-RT0: R87.1 U1.R3 | length 771.3
  Top w8: U1.R3@2355.86,2180 v2(2337.9,2180.1) U1.R3@2355.86,2180.1
  Top w10: U1.R3@2355.86,2180 U1.R3@2355.86,2180.1
  Bottom w4.5: R87.1@1866.22,1960.76 1889.5,1964 ; R87.1@1866.22,1967.24 1889.5,1964 ; R87.1@1867.28,1956.36 1889.5,1964 ; R87.1@1867.28,1971.64 1889.5,1964 ; v2@2336.69,2185.72 2322.15,2179.65 ; v2@2337.01,2174.42 2322.15,2179.65 ; 1889.5,1964 R87.1@1866,1964 1865,1964 1870,1969 1870,1964 1959,1964 2072.75,2077.75 2220.25,2077.75 2322.15,2179.65 ; 2322.15,2179.65 2337.45,2179.65 v2(2337.9,2180.1) 2322.15,2179.65
MA12_1-CPU-RT0: R89.1 U1.P5 | length 843.4
  Top w4: v2@2370.42,2148.82 2392.75,2161.65 ; v2@2378.59,2140.14 2392.75,2161.65 ; U1.P5@2409.7,2158.02 2393,2161.9 ; U1.P5@2409.7,2165.78 2393,2161.9 ; 2392.75,2161.65 v2(2374,2144) 2375.1,2144 2393,2161.9 ; 2393,2161.9 U1.P5@2410.14,2161.9 2393,2161.9
  Bottom w4.5: R89.1@2092,1750 2125,1750 2245,1870 2245,1965 2374,2094 v2(2374,2144) ; R89.1@2092.22,1746.76 2115.5,1750 ; R89.1@2092.22,1753.24 2115.5,1750 ; R89.1@2093.28,1742.36 2115.5,1750 ; R89.1@2093.28,1757.64 2115.5,1750 ; v2@2368.29,2143.3 2374,2120.5 v2@2379.71,2143.3
MA13_1-CPU-RT0: R826.1 U1.N5 | length 889.9
  Top w4.5: v2@2406.43,2148.51 2427.6,2161.6 ; v2(2410,2144) 2427.6,2161.6 ; v2@2414.51,2140.43 2427.6,2161.6 ; U1.N5@2424.59,2179.76 2427.6,2161.6 ; U1.N5@2431.86,2179.51 2427.6,2161.6 ; 2427.6,2161.6 2427.6,2179.36 U1.N5@2428.24,2180 2427.6,2161.6
  Bottom w4.5: R826.1@1937.09,1983.75 1960.52,1986 ; R826.1@1937.36,1990.23 1960.52,1986 ; R826.1@1937.95,1979.31 1960.52,1986 ; R826.1@1938.6,1994.58 1960.52,1986 ; v2@2408.31,2138.51 2397,2145 ; v2@2409.17,2149.69 2397,2145 ; 1960.52,1986 R826.1@1937,1987 1936,1987 1936,1986 1961,1986 2065,2090 2218,2090 2324,2196 2346,2196 2397,2145 ; 2397,2145 2409,2145 v2(2410,2144) 2397,2145
MADDR0: R65.2 U22.M8 | length 540.6
  Top w4: v2@1692.61,2096.54 U22.M8@1690.91,2115.62 ; v2@1693.33,2094.84 U22.M8@1686.04,2112.33 ; v2@1693.45,2094.66 U22.M8@1685.56,2111.85 ; v2@1694.54,2093.43 U22.M8@1682.41,2107.72 ; v2@1700.68,2103.56 U22.M8@1682.41,2107.72 ; v2@1702.12,2102.73 U22.M8@1685.56,2111.85 ; v2@1702.29,2102.59 U22.M8@1686.04,2112.33 ; v2@1703.51,2101.19 U22.M8@1690.91,2115.62 ; U22.M8@1682.41,2107.72 v2@1698.92,2098.49 ; U22.M8@1682.41,2107.72 v2(1698.43,2098) ; U22.M8@1685.56,2111.85 U22.M8@1686.04,2112.33 ; U22.M8@1685.56,2111.85 v2@1698.92,2098.49 ; U22.M8@1685.56,2111.85 v2(1698.43,2098) ; U22.M8@1686.04,2112.33 v2@1698.92,2098.49 ; U22.M8@1686.04,2112.33 v2(1698.43,2098) ; U22.M8@1690.91,2115.62 v2@1698.92,2098.49 ; U22.M8@1690.91,2115.62 v2(1698.43,2098) ; v2(1698.43,2098) v2@1698.92,2098.49
  Bottom w4.5: v2(1698.43,2098) 1711.12,2098 ; v2@1699.74,2092.4 1711.12,2098 ; v2@1699.74,2103.6 1711.12,2098 ; R65.2@1828.38,2077.42 1811.5,2085 ; R65.2@1828.38,2092.58 1811.5,2085 ; R65.2@1829.71,2081.76 1811.5,2085 ; R65.2@1829.71,2088.24 1811.5,2085 ; R65.2@1830,2085 1811.5,2085 ; 1711.12,2098 1720.12,2089 1807.5,2089 1811.5,2085
MADDR1: R67.2 U22.M3 | length 1080.2
  Top w4.5: v2@1509.53,2101.39 U22.M3@1524.08,2115.73 ; v2@1510.44,2102.34 U22.M3@1527.1,2112.33 ; v2@1510.65,2102.5 U22.M3@1528.56,2112.33 ; v2@1512.04,2103.27 U22.M3@1531.95,2107.84 ; v2@1517.58,2093.32 U22.M3@1531.95,2107.84 ; v2@1518.69,2094.44 U22.M3@1528.56,2112.33 ; v2@1518.9,2094.73 U22.M3@1527.1,2112.33 ; v2@1519.46,2095.83 U22.M3@1524.08,2115.73 ; v2(1514.1,2097.9) U22.M3@1527.1,2112.33 ; v2(1514.1,2097.9) U22.M3@1531.95,2107.84 ; v2(1514.1,2097.9) U22.M3@1524.08,2115.73 ; v2(1514.1,2097.9) U22.M3@1528.56,2112.33 ; U22.M3@1527.1,2112.33 U22.M3@1528.56,2112.33
  Bottom w4.5: v2@1511.42,2092.81 1537.83,2082.17 ; v2@1517.74,2102.35 1537.83,2082.17 ; R67.2@1985.82,1812.44 1963.94,1802 ; R67.2@1987.38,1808.19 1963.94,1802 ; R67.2@1987.72,1797.25 1963.94,1802 ; R67.2@1988.19,1801.75 1963.94,1802 ; 1537.83,2082.17 v2(1514.1,2097.9) 1522.1,2097.9 1567.9,2052.1 1567.9,1997.1 1763,1802 1985,1802 R67.2@1988,1805 1963.94,1802
MADDR2: R69.2 U22.M7 | length 630.6
  Top w4: v2@1661.21,2097.44 U22.M7@1659.43,2115.6 ; v2@1662,2095.68 U22.M7@1654.55,2112.33 ; v2@1662.1,2095.54 U22.M7@1654.55,2111.45 ; v2@1663.31,2094.27 U22.M7@1650.95,2107.69 ; v2@1668.95,2104.67 U22.M7@1650.95,2107.69 ; v2@1670.46,2103.9 U22.M7@1654.55,2111.45 ; v2@1670.65,2103.76 U22.M7@1654.55,2112.33 ; v2@1671.98,2102.35 U22.M7@1659.43,2115.6 ; U22.M7@1650.95,2107.69 v2(1667,2099) ; U22.M7@1654.55,2111.45 U22.M7@1654.55,2112.33 ; U22.M7@1654.55,2111.45 v2(1667,2099) ; U22.M7@1654.55,2112.33 v2(1667,2099) ; U22.M7@1659.43,2115.6 v2(1667,2099)
  Bottom w4.5: v2@1663.45,2094.48 1684,2082 ; v2(1667,2099) 1684,2082 ; v2@1671.52,2102.55 1684,2082 ; R69.2@1898.72,2057.36 1876.5,2065 ; R69.2@1898.72,2072.64 1876.5,2065 ; R69.2@1899.78,2061.76 1876.5,2065 ; R69.2@1899.78,2068.24 1876.5,2065 ; 1684,2082 1709.63,2082 1717.63,2074 1808,2074 1817,2065 R69.2@1900,2065 1876.5,2065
